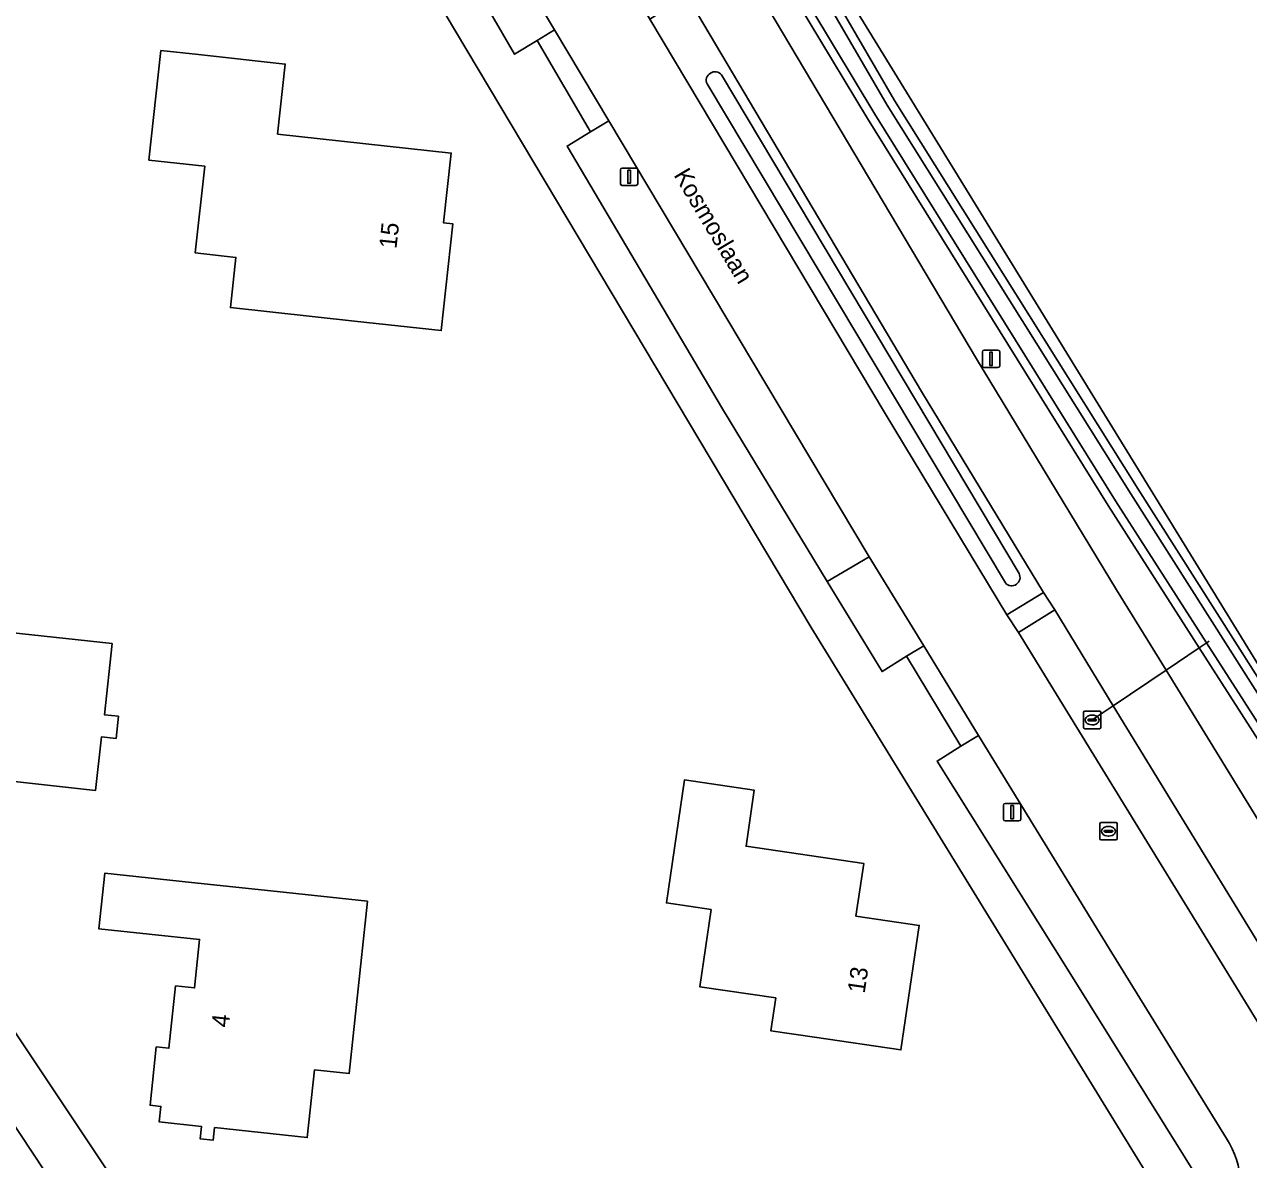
# Model space of a CAD drawing. Extents: x 162396 to 163643, y 386452 to 387406.
# Drawn here: x 163078.6 to 163148.6, y 386829.1 to 386894 of the extents above; entities that cross this region are included whole.
import ezdxf

# ---------------------------------------------------------------- set-up
doc = ezdxf.new("R2010")
doc.units = 0
for name, color, linetype in [('IMGEO_Berm_groen', 7, 'Continuous'), ('IMGEO_Duiker', 7, 'Continuous'), ('IMGEO_Erf', 7, 'Continuous'), ('IMGEO_Fietspad_gesloten', 7, 'Continuous'), ('IMGEO_Fietspad_halfverhard', 7, 'Continuous'), ('IMGEO_Grasland_agrarisch', 7, 'Continuous'), ('IMGEO_Greppel_droge_sloot', 7, 'Continuous'), ('IMGEO_Hek', 7, 'Continuous'), ('IMGEO_Lichtmast', 7, 'Continuous'), ('IMGEO_Oever', 7, 'Continuous'), ('IMGEO_Openbare_ruimte_label', 7, 'Continuous'), ('IMGEO_Pand', 7, 'Continuous'), ('IMGEO_Pand_nummerreeks', 7, 'Continuous'), ('IMGEO_Parkeervlak_halfverhard', 7, 'Continuous'), ('IMGEO_Rijbaan_lokaal_gesloten', 7, 'Continuous'), ('IMGEO_Rijbaan_lokaal_open', 7, 'Continuous'), ('IMGEO_Rioolput', 7, 'Continuous'), ('IMGEO_Voetpad_open', 7, 'Continuous')]:
    doc.layers.add(name, color=color, linetype=linetype)

msp = doc.modelspace()

# ---------------------------------------------------------------- linework, layer by layer
at = {"layer": 'IMGEO_Berm_groen'}
for points in [[(163058.321, 387013.033), (163062.245, 387003.85), (163065.679, 386996.007), (163072.387, 386981.888), (163076.252, 386973.982), (163079.946, 386966.717), (163082.017, 386962.946), (163085.197, 386957.174), (163087.753, 386952.543), (163088.198, 386951.737), (163088.644, 386950.931), (163089.035, 386950.226), (163090.045, 386948.352), (163091.713, 386945.359), (163103.715, 386924.646), (163109.912, 386913.996), (163113.552, 386907.796), (163119.49, 386897.68), (163133.047, 386874.854), (163141.068, 386861.652), (163143.895, 386857.051), (163155.065, 386838.871)], [(163153.066, 386846.995), (163145.801, 386858.335), (163140.584, 386866.478), (163126.817, 386888.603), (163114.805, 386908.538), (163112.488, 386912.383), (163096.88, 386939.306)], [(163118.465, 386891.104), (163135.484, 386862.577)], [(163134.708, 386862.04), (163117.633, 386890.586)], [(163137.525, 386860.5), (163135.447, 386859.2), (163152.596, 386831.287)], [(163156.522, 386829.586), (163151.706, 386837.322), (163140.88, 386855.017), (163137.525, 386860.5)], [(163133.171, 386853.318), (163132.152, 386852.695), (163130.798, 386851.848), (163138.449, 386839.645), (163146.104, 386827.388), (163148.158, 386827.738)], [(163147.359, 386830.262), (163140.649, 386841.134), (163133.171, 386853.318)]]:
    msp.add_lwpolyline(points, dxfattribs=at)
for points in [[(163116.481, 386895.637), (163114.367, 386894.296), (163127.83, 386871.73), (163134.797, 386860.218), (163136.893, 386861.494), (163129.911, 386872.986)], [(163112.007, 386888.479), (163110.973, 386887.848), (163109.622, 386887.031), (163118.528, 386872), (163124.5, 386862.121), (163126.92, 386863.539), (163120.994, 386873.425)]]:
    msp.add_lwpolyline(points, close=True, dxfattribs=at)
for centre, radius, start, end in [((163118.084, 386890.789), 0.494, 39.57558, 204.23689), ((163135.068, 386862.35), 0.474, 220.73863, 28.62864), ((163143.164, 386827.546), 4.998, 2.20645, 32.92507)]:
    msp.add_arc(centre, radius, start, end, dxfattribs=at)
at = {"layer": 'IMGEO_Duiker'}
msp.add_lwpolyline([(163139.671, 386854.202), (163140.88, 386855.017), (163143.895, 386857.051), (163145.801, 386858.335), (163146.356, 386858.71)], dxfattribs=at)
at = {"layer": 'IMGEO_Erf'}
for points in [[(163143.068, 386827.803), (163123.585, 386859.49), (163102.006, 386895.698), (163079.761, 386934.958), (163074.122, 386945.175)], [(163007.354, 386901.067), (163015.139, 386898.602), (163026.263, 386893.389), (163036.995, 386887.184), (163041.525, 386884.206), (163044.924, 386881.491), (163048.697, 386878.147), (163052.273, 386874.373), (163055.371, 386870.345), (163099.918, 386803.497)]]:
    msp.add_lwpolyline(points, dxfattribs=at)
for points in [[(163086.385, 386892.497), (163088.532, 386892.262), (163093.502, 386891.719), (163093.065, 386887.719), (163102.997, 386886.634), (163102.56, 386882.638), (163103.092, 386882.58), (163102.425, 386876.476), (163097.455, 386877.019), (163090.36, 386877.794), (163090.674, 386880.664), (163088.352, 386880.918), (163088.895, 386885.886), (163085.701, 386886.234)], [(163076.757, 386863.368), (163076.324, 386859.354), (163083.595, 386858.569), (163083.155, 386854.498), (163083.957, 386854.411), (163083.82, 386853.142), (163082.979, 386853.233), (163082.649, 386850.175), (163078.003, 386850.676), (163073.031, 386851.212), (163073.584, 386856.332), (163069.229, 386856.802), (163070.016, 386864.095), (163074.988, 386863.559)], [(163120.339, 386850.185), (163119.869, 386846.98), (163126.598, 386845.992), (163126.155, 386842.981), (163129.774, 386842.45), (163128.728, 386835.325), (163123.782, 386836.051), (163121.289, 386836.417), (163121.566, 386838.303), (163117.219, 386838.941), (163117.868, 386843.357), (163115.306, 386843.733), (163116.34, 386850.772)], [(163093.032, 386844.385), (163098.202, 386843.834), (163097.57, 386837.93), (163097.15, 386833.976), (163095.173, 386834.186), (163094.762, 386830.315), (163089.459, 386830.879), (163089.383, 386830.166), (163088.63, 386830.246), (163088.704, 386830.946), (163086.288, 386831.203), (163086.382, 386832.094), (163085.768, 386832.159), (163086.122, 386835.494), (163086.843, 386835.417), (163087.223, 386838.99), (163088.308, 386838.875), (163088.602, 386841.643), (163082.831, 386842.256), (163083.168, 386845.433), (163088.141, 386844.905)]]:
    msp.add_lwpolyline(points, close=True, dxfattribs=at)
at = {"layer": 'IMGEO_Fietspad_gesloten'}
for points in [[(163155.065, 386838.871), (163143.895, 386857.051), (163141.068, 386861.652), (163133.047, 386874.854), (163119.49, 386897.68), (163113.552, 386907.796), (163109.912, 386913.996), (163103.715, 386924.646), (163091.713, 386945.359), (163090.045, 386948.352), (163089.035, 386950.226), (163088.644, 386950.931), (163088.198, 386951.737), (163087.753, 386952.543), (163085.197, 386957.174), (163082.017, 386962.946), (163079.946, 386966.717), (163076.252, 386973.982), (163072.387, 386981.888), (163065.679, 386996.007), (163062.245, 387003.85), (163058.321, 387013.033)], [(163081.061, 386957.239), (163084.489, 386950.829), (163086.516, 386947.047), (163094.302, 386933.576), (163094.886, 386932.55), (163100.492, 386922.911), (163106.699, 386912.218), (163110.406, 386905.934), (163115.894, 386896.629), (163116.481, 386895.637), (163129.911, 386872.986), (163136.893, 386861.494), (163137.525, 386860.5), (163140.88, 386855.017), (163151.706, 386837.322), (163156.522, 386829.586)]]:
    msp.add_lwpolyline(points, dxfattribs=at)
at = {"layer": 'IMGEO_Fietspad_halfverhard'}
msp.add_lwpolyline([(163137.525, 386860.5), (163136.893, 386861.494), (163134.797, 386860.218), (163135.447, 386859.2)], close=True, dxfattribs=at)
at = {"layer": 'IMGEO_Grasland_agrarisch'}
msp.add_lwpolyline([(163098.137, 386941.992), (163116.399, 386910.212), (163128.365, 386889.63), (163142.301, 386867.412), (163154.565, 386848.11), (163157.583, 386842.961), (163157.905, 386843.143), (163162.006, 386845.923), (163174.171, 386826.377), (163170.355, 386823.925), (163171.995, 386820.854), (163236.272, 386723.927)], dxfattribs=at)
at = {"layer": 'IMGEO_Greppel_droge_sloot'}
for points in [[(163097.315, 386939.553), (163112.918, 386912.637), (163115.235, 386908.793), (163127.243, 386888.864), (163141.007, 386866.745), (163146.215, 386858.615), (163153.49, 386847.26), (163159.708, 386837.054), (163160.184, 386837.158), (163160.318, 386837.307), (163157.295, 386842.465), (163157.152, 386842.708), (163154.138, 386847.849), (163141.878, 386867.145), (163127.937, 386889.371), (163115.966, 386909.962), (163097.705, 386941.74)], [(163135.484, 386862.577), (163118.465, 386891.104)], [(163117.633, 386890.586), (163134.708, 386862.04)]]:
    msp.add_lwpolyline(points, dxfattribs=at)
for centre, radius, start, end in [((163118.084, 386890.789), 0.494, 39.57558, 204.23689), ((163135.068, 386862.35), 0.474, 220.73863, 28.62864)]:
    msp.add_arc(centre, radius, start, end, dxfattribs=at)
at = {"layer": 'IMGEO_Hek'}
msp.add_lwpolyline([(163157.905, 386843.143), (163119.211, 386906.146)], dxfattribs=at)
at = {"layer": 'IMGEO_Lichtmast'}
for p, q in [((163112.679, 386884.876), (163112.679, 386885.676)), ((163112.679, 386885.676), (163112.679, 386884.876)), ((163112.779, 386885.776), (163113.569, 386885.776)), ((163113.569, 386885.776), (163112.779, 386885.776)), ((163113.669, 386885.676), (163113.669, 386884.876)), ((163113.669, 386884.876), (163113.669, 386885.676)), ((163113.569, 386884.776), (163112.779, 386884.776)), ((163112.779, 386884.776), (163113.569, 386884.776)), ((163133.388, 386874.46), (163133.388, 386875.26)), ((163133.388, 386875.26), (163133.388, 386874.46)), ((163133.488, 386875.36), (163134.278, 386875.36)), ((163134.278, 386875.36), (163133.488, 386875.36)), ((163134.378, 386875.26), (163134.378, 386874.46)), ((163134.378, 386874.46), (163134.378, 386875.26)), ((163134.278, 386874.36), (163133.488, 386874.36)), ((163133.488, 386874.36), (163134.278, 386874.36)), ((163134.592, 386848.529), (163134.592, 386849.329)), ((163134.592, 386849.329), (163134.592, 386848.529)), ((163134.692, 386849.429), (163135.482, 386849.429)), ((163135.482, 386849.429), (163134.692, 386849.429)), ((163135.582, 386849.329), (163135.582, 386848.529)), ((163135.582, 386848.529), (163135.582, 386849.329)), ((163135.482, 386848.429), (163134.692, 386848.429)), ((163134.692, 386848.429), (163135.482, 386848.429))]:
    msp.add_line(p, q, dxfattribs=at)
for points in [[(163113.099, 386885.651), (163113.249, 386885.651), (163113.249, 386884.901), (163113.099, 386884.901), (163113.099, 386885.651)], [(163133.808, 386875.235), (163133.958, 386875.235), (163133.958, 386874.485), (163133.808, 386874.485), (163133.808, 386875.235)], [(163135.012, 386849.304), (163135.162, 386849.304), (163135.162, 386848.554), (163135.012, 386848.554), (163135.012, 386849.304)]]:
    msp.add_lwpolyline(points, dxfattribs=at)
for centre, start, end in [((163112.779, 386885.676), 90, 180), ((163112.779, 386885.676), 90, 180), ((163113.569, 386885.676), 0, 90), ((163113.569, 386885.676), 360, 90), ((163112.779, 386884.876), 180, 270), ((163112.779, 386884.876), 180, 270), ((163113.569, 386884.876), 270, 0), ((163113.569, 386884.876), 270, 0), ((163133.488, 386875.26), 90, 180), ((163133.488, 386875.26), 90, 180), ((163134.278, 386875.26), 0, 90), ((163134.278, 386875.26), 360, 90), ((163133.488, 386874.46), 180, 270), ((163133.488, 386874.46), 180, 270), ((163134.278, 386874.46), 270, 0), ((163134.278, 386874.46), 270, 0), ((163134.692, 386849.329), 90, 180), ((163134.692, 386849.329), 90, 180), ((163135.482, 386849.329), 0, 90), ((163135.482, 386849.329), 360, 90), ((163134.692, 386848.529), 180, 270), ((163134.692, 386848.529), 180, 270), ((163135.482, 386848.529), 270, 0), ((163135.482, 386848.529), 270, 0)]:
    msp.add_arc(centre, 0.1, start, end, dxfattribs=at)
at = {"layer": 'IMGEO_Oever'}
for points in [[(163089.008, 386953.161), (163092.32, 386947.094), (163093.973, 386944.513), (163096.88, 386939.306), (163112.488, 386912.383), (163114.805, 386908.538), (163126.817, 386888.603), (163140.584, 386866.478), (163145.801, 386858.335), (163153.066, 386846.995), (163159.466, 386836.49), (163160.448, 386836.704), (163160.934, 386837.244), (163157.726, 386842.718), (163157.583, 386842.961), (163154.565, 386848.11), (163142.301, 386867.412), (163128.365, 386889.63), (163116.399, 386910.212), (163098.137, 386941.992)], [(163097.705, 386941.74), (163115.966, 386909.962), (163127.937, 386889.371), (163141.878, 386867.145), (163154.138, 386847.849), (163157.152, 386842.708), (163157.295, 386842.465), (163160.318, 386837.307), (163160.184, 386837.158), (163159.708, 386837.054), (163153.49, 386847.26), (163146.215, 386858.615), (163141.007, 386866.745), (163127.243, 386888.864), (163115.235, 386908.793), (163112.918, 386912.637), (163097.315, 386939.553)]]:
    msp.add_lwpolyline(points, dxfattribs=at)
at = {"layer": 'IMGEO_Pand'}
for points in [[(163086.385, 386892.497), (163085.701, 386886.234), (163088.895, 386885.886), (163088.352, 386880.918), (163090.674, 386880.664), (163090.36, 386877.794), (163097.455, 386877.019), (163102.425, 386876.476), (163103.092, 386882.58), (163102.56, 386882.638), (163102.997, 386886.634), (163093.065, 386887.719), (163093.502, 386891.719), (163088.532, 386892.262)], [(163074.988, 386863.559), (163070.016, 386864.095), (163069.229, 386856.802), (163073.584, 386856.332), (163073.031, 386851.212), (163078.003, 386850.676), (163082.649, 386850.175), (163082.979, 386853.233), (163083.82, 386853.142), (163083.957, 386854.411), (163083.155, 386854.498), (163083.595, 386858.569), (163076.324, 386859.354), (163076.757, 386863.368)], [(163116.34, 386850.772), (163115.306, 386843.733), (163117.868, 386843.357), (163117.219, 386838.941), (163121.566, 386838.303), (163121.289, 386836.417), (163123.782, 386836.051), (163128.728, 386835.325), (163129.774, 386842.45), (163126.155, 386842.981), (163126.598, 386845.992), (163119.869, 386846.98), (163120.339, 386850.185)], [(163097.57, 386837.93), (163098.202, 386843.834), (163093.032, 386844.385), (163088.141, 386844.905), (163083.168, 386845.433), (163082.831, 386842.256), (163088.602, 386841.643), (163088.308, 386838.875), (163087.223, 386838.99), (163086.843, 386835.417), (163086.122, 386835.494), (163085.768, 386832.159), (163086.382, 386832.094), (163086.288, 386831.203), (163088.704, 386830.946), (163088.63, 386830.246), (163089.383, 386830.166), (163089.459, 386830.879), (163094.762, 386830.315), (163095.173, 386834.186), (163097.15, 386833.976)]]:
    msp.add_lwpolyline(points, close=True, dxfattribs=at)
at = {"layer": 'IMGEO_Parkeervlak_halfverhard'}
for points in [[(163105.855, 386898.787), (163103.597, 386897.495), (163106.622, 386892.28), (163107.915, 386893.07), (163108.904, 386893.677)], [(163126.92, 386863.539), (163124.5, 386862.121), (163127.647, 386856.97), (163129.05, 386857.843), (163130.045, 386858.445)]]:
    msp.add_lwpolyline(points, close=True, dxfattribs=at)
at = {"layer": 'IMGEO_Rijbaan_lokaal_gesloten'}
for points in [[(163100.8, 386907.449), (163105.855, 386898.787), (163108.904, 386893.677), (163112.007, 386888.479), (163120.994, 386873.425), (163126.92, 386863.539), (163130.045, 386858.445), (163133.171, 386853.318), (163140.649, 386841.134), (163147.359, 386830.262)], [(163152.596, 386831.287), (163135.447, 386859.2), (163134.797, 386860.218), (163127.83, 386871.73), (163114.367, 386894.296), (163113.745, 386895.358), (163111.839, 386898.512)]]:
    msp.add_lwpolyline(points, dxfattribs=at)
msp.add_arc((163143.164, 386827.546), 4.998, 2.20645, 32.92507, dxfattribs=at)
at = {"layer": 'IMGEO_Rijbaan_lokaal_open'}
for points in [[(163108.904, 386893.677), (163107.915, 386893.07), (163110.973, 386887.848), (163112.007, 386888.479)], [(163130.045, 386858.445), (163129.05, 386857.843), (163132.152, 386852.695), (163133.171, 386853.318)]]:
    msp.add_lwpolyline(points, close=True, dxfattribs=at)
msp.add_lwpolyline([(163084.661, 386820.941), (163072.682, 386839.022), (163070.601, 386842.162), (163058.066, 386861.082), (163055.939, 386864.293), (163054.925, 386865.823), (163051.94, 386869.963), (163048.719, 386873.794), (163045.549, 386876.981)], dxfattribs=at)
at = {"layer": 'IMGEO_Rioolput'}
for p, q in [((163139.17, 386853.776), (163139.17, 386854.628)), ((163139.245, 386854.702), (163140.097, 386854.702)), ((163139.658, 386854.482), (163139.683, 386854.482)), ((163140.171, 386854.628), (163140.171, 386853.776)), ((163139.429, 386854.196), (163139.429, 386854.208)), ((163139.867, 386854.159), (163139.469, 386854.159)), ((163139.472, 386854.245), (163139.87, 386854.245)), ((163139.681, 386853.922), (163139.656, 386853.922)), ((163139.913, 386854.208), (163139.913, 386854.196)), ((163140.097, 386853.702), (163139.245, 386853.702)), ((163140.106, 386847.409), (163140.106, 386848.261)), ((163140.181, 386848.335), (163141.033, 386848.335)), ((163141.107, 386848.261), (163141.107, 386847.409)), ((163140.365, 386847.829), (163140.365, 386847.841)), ((163140.803, 386847.792), (163140.405, 386847.792)), ((163140.408, 386847.878), (163140.806, 386847.878)), ((163140.617, 386847.555), (163140.592, 386847.555)), ((163140.594, 386848.115), (163140.619, 386848.115)), ((163140.849, 386847.841), (163140.849, 386847.829)), ((163141.033, 386847.335), (163140.181, 386847.335))]:
    msp.add_line(p, q, dxfattribs=at)
for points in [[(163139.17, 386853.776), (163139.17, 386854.628)], [(163139.245, 386854.702), (163140.097, 386854.702)], [(163140.171, 386854.628), (163140.171, 386853.776)], [(163140.097, 386853.702), (163139.245, 386853.702)], [(163140.106, 386847.409), (163140.106, 386848.261)], [(163140.181, 386848.335), (163141.033, 386848.335)], [(163141.107, 386848.261), (163141.107, 386847.409)], [(163141.033, 386847.335), (163140.181, 386847.335)]]:
    msp.add_lwpolyline(points, dxfattribs=at)
for centre, radius, start, end in [((163139.247, 386854.626), 0.0765, 91.55205, 178.44795), ((163139.247, 386854.626), 0.0765, 91.55205, 178.44795), ((163140.095, 386854.626), 0.0765, 1.55205, 88.44795), ((163140.095, 386854.626), 0.0765, 1.55205, 88.44795), ((163139.247, 386853.778), 0.0765, 181.55205, 268.44795), ((163139.247, 386853.778), 0.0765, 181.55205, 268.44795), ((163139.469, 386854.205), 0.0403, 85.87752, 175.75265), ((163139.466, 386854.195), 0.0366, 178.93798, 274.71019), ((163139.87, 386854.202), 0.043, 264.86636, 352.45326), ((163139.874, 386854.207), 0.0386, 1.73085, 96.63898), ((163140.095, 386853.778), 0.0765, 271.55205, 358.44795), ((163140.095, 386853.778), 0.0765, 271.55205, 358.44795), ((163140.183, 386848.259), 0.0765, 91.55205, 178.44795), ((163140.183, 386848.259), 0.0765, 91.55205, 178.44795), ((163141.031, 386848.259), 0.0765, 1.55205, 88.44795), ((163141.031, 386848.259), 0.0765, 1.55205, 88.44795), ((163140.405, 386847.838), 0.0403, 85.87752, 175.75265), ((163140.402, 386847.828), 0.0366, 178.93798, 274.71019), ((163140.806, 386847.835), 0.043, 264.86636, 352.45326), ((163140.81, 386847.84), 0.0386, 1.73085, 96.63898), ((163140.183, 386847.411), 0.0765, 181.55205, 268.44795), ((163140.183, 386847.411), 0.0765, 181.55205, 268.44795), ((163141.031, 386847.411), 0.0765, 271.55205, 358.44795), ((163141.031, 386847.411), 0.0765, 271.55205, 358.44795)]:
    msp.add_arc(centre, radius, start, end, dxfattribs=at)
for centre, major_axis, ratio, start_param, end_param in [((163139.657, 386854.202), (-0.387, 0.002), 0.722429, 4.712389, 7.853982), ((163139.682, 386854.202), (-0.39, 0.002), 0.717154, 1.570796, 4.712389), ((163140.593, 386847.835), (-0.387, 0.002), 0.722429, 4.712389, 7.853982), ((163140.618, 386847.835), (-0.39, 0.002), 0.717154, 1.570796, 4.712389)]:
    msp.add_ellipse(centre, major_axis=major_axis, ratio=ratio, start_param=start_param, end_param=end_param, dxfattribs=at)
at = {"layer": 'IMGEO_Voetpad_open'}
for points in [[(163016.462, 387091.359), (163024.497, 387061.137), (163030.729, 387041.536), (163041.387, 387012.856), (163042.57, 387009.785), (163046.866, 387000), (163053.248, 386986.028), (163057.319, 386977.598), (163067.344, 386957.823), (163074.122, 386945.175), (163079.761, 386934.958), (163102.006, 386895.698), (163123.585, 386859.49), (163143.068, 386827.803)], [(163148.158, 386827.738), (163146.104, 386827.388), (163138.449, 386839.645), (163130.798, 386851.848), (163132.152, 386852.695), (163129.05, 386857.843), (163127.647, 386856.97), (163124.5, 386862.121), (163118.528, 386872), (163109.622, 386887.031), (163110.973, 386887.848), (163107.915, 386893.07), (163106.622, 386892.28), (163103.597, 386897.495), (163094.586, 386913.257), (163089.68, 386921.904), (163090.714, 386922.504), (163086.703, 386929.474), (163085.725, 386928.948), (163082.833, 386934.162), (163075.976, 386946.453)], [(163099.918, 386803.497), (163055.371, 386870.345), (163052.273, 386874.373), (163048.697, 386878.147), (163044.924, 386881.491), (163041.525, 386884.206), (163036.995, 386887.184), (163026.263, 386893.389), (163015.139, 386898.602)], [(163045.549, 386876.981), (163048.719, 386873.794), (163051.94, 386869.963), (163054.925, 386865.823), (163055.939, 386864.293), (163058.066, 386861.082), (163070.601, 386842.162), (163072.682, 386839.022), (163084.661, 386820.941), (163086.459, 386818.227), (163088.943, 386814.478), (163089.654, 386813.404), (163097.59, 386801.208), (163098.684, 386799.487), (163098.774, 386799.346), (163099.704, 386798.039)]]:
    msp.add_lwpolyline(points, dxfattribs=at)

# ---------------------------------------------------------------- texts
at = {"layer": 'IMGEO_Openbare_ruimte_label'}
msp.add_text('Kosmoslaan', height=1, rotation=300.79671, dxfattribs=at).set_placement((163115.7, 386885.378))
at = {"layer": 'IMGEO_Pand_nummerreeks'}
for s, rotation, p in [('15', 83.75897, (163099.86, 386881.127)), ('13', 81.64824, (163126.651, 386838.526)), ('4', 83.92923, (163090.265, 386836.583))]:
    msp.add_text(s, height=1, rotation=rotation, dxfattribs=at).set_placement(p)

doc.saveas('drawing.dxf')
